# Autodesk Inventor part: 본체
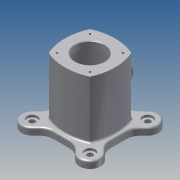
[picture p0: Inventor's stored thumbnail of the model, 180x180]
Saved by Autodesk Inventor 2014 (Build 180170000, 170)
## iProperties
Created: 2016-05
Part Number: 본체
Material: 알루미늄 6061
Document SubType Name: Modeling
Designer: 702
Density: 2.71 g/cm^3
Appearance: 알루미늄 - 평지
Mass: 1109.03 g
Surface Area: 865.354 cm^2
Volume: 409.236 cm^3
Author: 702
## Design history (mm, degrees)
sketch "스케치1"
  geometry: L1 (-49, -49)-(49, -49); L2 (49, -49)-(49, 49); L3 (49, 49)-(-49, 49); L4 (-49, 49)-(-49, -49); L5 (-49, -49)-(49, 49); L6 (49, -49)-(-49, 49); L7 (0, 0)-(-70, 0); L8 (0, 0)-(-49.497, 49.497); L9 (-36.77, 62.225)-(-23.544, 49); L10 (-62.225, 36.77)-(-49, 23.544); L11 (-49, 23.544)-(-49, 49); L12 (-49, 49)-(-23.544, 49); A1 r 70 centre (0, 0) between (-70, 0) and (-49.497, 49.497); A2 r 18 centre (-49.497, 49.497) between (-35.239, 60.483) and (-60.483, 35.239); A3 r 18 centre (-49.497, 49.497) between (-31.504, 49) and (-35.239, 60.483); A4 r 18 centre (-49.497, 49.497) between (-49, 31.504) and (-31.504, 49); A5 r 18 centre (-49.497, 49.497) between (-60.483, 35.239) and (-49, 31.504); 1 further point
  constraints: 24 end point, 18 point on circle, 6 tangent, 5 centre point, 4 midpoint, 4 point on line, 2 coincident, 2 collinear, 2 parallel, 2 perpendicular, 1 horizontal
  dimensions: "d0" = 98 distance of L2.end L3.end; "d1" = 98 distance of L1.end L2.end; "d2" = 140 diameter of A1; "d3" = 45 deg angle of L7 L8; "d4" = 36 diameter of A2; "d5" = 45 deg angle of L3 L9; "d6" = 45 deg angle of L10 L4
extrude "돌출1" new body sketch "스케치1" distance "d7" = 12; taper "d8" = 0 deg
extrude "돌출2" join sketch "스케치1" distance "d9" = 12; taper "d10" = 0 deg
hole "구멍1" diameter "d13" = 10; stored, may be unused: countersink angle "d17" = 90 deg, drill point angle "d19" = 118 deg; dims "d11" = 10, "d12" = 10, "d14" = 6, "d15" = 18, "d16" = 4, "d18" = 8
sketch "스케치3"
  geometry: L1 (-23.544, -49)-(-36.77, -62.225) reference; L2 (23.544, -49)-(-23.544, -49) reference; L3 (-40, 0)-(0, 0); L4 (0, 0)-(-28.284, 28.284); A1 r 40 centre (0, 0) between (-40, 0) and (-28.284, 28.284); 2 further points
  constraints: 4 end point, 2 coincident, 2 point on circle, 1 centre point, 1 parallel, 1 perpendicular
  dimensions: "d24" = 80 diameter of A1
hole "구멍2" sketch "스케치3" at (-28.284, 28.284) diameter "d25" = 3.242; stored, may be unused: countersink angle "d29" = 90 deg, drill point angle "d31" = 118 deg; dims "d26" = 7, "d27" = 4, "d28" = 2, "d30" = 10
sketch "스케치4"
  geometry: L1 (43, -43)-(-43, -43); L2 (-43, -43)-(-43, 43); L3 (-43, 43)-(43, 43); L4 (43, 43)-(43, -43); L5 (43, -43)-(-43, 43); L6 (-43, -43)-(43, 43); L7 (-35.355, -35.355)-(35.355, 35.355); L8 (-35.355, 35.355)-(35.355, -35.355); L9 (-23.544, -49)-(23.544, -49); L10 (-36.77, -62.225)-(-23.544, -49) reference; A1 r 85.579 centre (0, -42.579) between (35.355, 35.355) and (-35.355, 35.355); A2 r 85.579 centre (42.579, 0) between (-35.355, 35.355) and (-35.355, -35.355); A3 r 85.579 centre (-42.579, 0) between (35.355, -35.355) and (35.355, 35.355); A4 r 85.579 centre (0, 42.579) between (-35.355, -35.355) and (35.355, -35.355); 3 further points
  constraints: 18 end point, 8 point on circle, 6 midpoint, 4 centre point, 4 point on line, 4 tangent, 2 collinear, 2 parallel, 1 perpendicular
  dimensions: "d43" = 86 distance of L2.end L3.end; "d44" = 86 distance of L3.end L1.start; "d52" = 100 distance of L7.end L7.start; "d53" = 100 distance of L8.start L8.end
extrude "돌출3" join sketch "스케치4" distance "d54" = 98; taper "d55" = 0 deg
sketch "스케치5"
  geometry: L1 (-49, 0)-(-49, 12) reference; L2 (-49, 12)-(-43, 12) reference; L3 (-43, 110)-(43, 110) reference; L4 (43, 110)-(43, 12) reference; L5 (43, 12)-(49, 12) reference; L6 (49, 12)-(49, 0) reference; L7 (49, 0)-(-49, 0) reference; L8 (-49, 0)-(-49, 12) reference; L9 (-49, 12)-(-43, 12) reference; L10 (-43, 110)-(43, 110) reference; L11 (43, 110)-(43, 12) reference; L12 (43, 12)-(49, 12) reference; L13 (49, 12)-(49, 0) reference; L14 (49, 0)-(-49, 0) reference; L15 (25, 110)-(25, 98); L16 (25, 98)-(35, 98); L17 (35, 98)-(35, 12); L18 (35, 12)-(25, 12); L19 (25, 12)-(25, 0); L20 (0, 0)-(0, 110); L21 (-43, 12)-(-43, 110) reference; L22 (-43, 12)-(-43, 110) reference
  constraints: 12 end point, 3 parallel, 2 perpendicular, 2 point on line, 1 collinear, 1 midpoint
  dimensions: "d60" = 12 distance between parallel lines of L16 L3; "d61" = 12 distance of L18.end L19.end; "d62" = 86 distance of L16.end L17.end (derived); "d63" = 25 distance between parallel lines of L20 L15; "d64" = 35 distance between parallel lines of L20 L17; "d65" = 25 distance between parallel lines of L20 L19
revolve "회전1" sketch "스케치5" stored, may be unused: angle "d66" = 90 deg
sketch "스케치6" dims "d67" = 80
  geometry: L1 (-42.579, 0)-(0, 0); L2 (-35.355, 35.355)-(0, 0); C1 r 25 at (0, 0) reference; A1 r 85.579 centre (-42.579, 0) between (35.355, -35.355) and (35.355, 35.355) reference; 2 further points
  constraints: 4 end point, 1 coincident, 1 horizontal, 1 point on line, 3 other
hole "구멍3" sketch "스케치6" at (-28.284, 28.284) diameter "d68" = 3.242; stored, may be unused: countersink angle "d72" = 90 deg, drill point angle "d74" = 118 deg; dims "d69" = 7, "d70" = 4, "d71" = 2, "d73" = 10
sketch "스케치7"
  geometry: L1 (49, 12)-(49, 0) reference; L2 (49, 0)-(25, 0) reference; L3 (25, 0)-(25, 12) reference; L4 (25, 12)-(35, 12) reference; L5 (35, 12)-(35, 98) reference; L6 (35, 98)-(25, 98) reference; L7 (25, 98)-(25, 110) reference; L8 (25, 110)-(43, 110) reference; L9 (43, 110)-(43, 12) reference; L10 (43, 12)-(49, 12) reference; L11 (-49, 0)-(-49, 12) reference; L12 (-49, 12)-(-43, 12) reference; L13 (-43, 110)-(-25, 110) reference; L14 (-25, 110)-(-25, 98) reference; L15 (-25, 98)-(-35, 98) reference; L16 (-35, 98)-(-35, 12) reference; L17 (-35, 12)-(-25, 12) reference; L18 (-25, 12)-(-25, 0) reference; L19 (-25, 0)-(-49, 0) reference; L20 (35, 84.527)-(55, 81); L21 (55, 81)-(55, 61); L22 (55, 61)-(35, 61); L23 (-43, 12)-(-43, 110) reference; 1 further point
  constraints: 6 end point, 2 perpendicular, 2 point on line
  dimensions: "d79" = 49 distance between parallel lines of L8 L22; "d81" = 100 deg angle of L5 L20; "d82" = 55 distance from line of point (0, 0) L21; "d93" = 20 distance of L20.end L21.end
revolve "회전2" sketch "스케치7" stored, may be unused: angle "d83" = 90 deg
hole "구멍4" diameter "d86" = 25; stored, may be unused: countersink angle "d90" = 90 deg, drill point angle "d92" = 118 deg; dims "d84" = 10, "d85" = 10, "d87" = 7, "d88" = 30, "d89" = 8, "d91" = 50
fillet "모깎기1" dims "d94" = 25
fillet "모깎기2" dims "d95" = 3
fillet "모깎기3" dims "d96" = 3
fillet "모깎기4" dims "d97" = 3
fillet "모깎기5" dims "d98" = 3
chamfer "모따기1" distance "d99" = 1; stored, may be unused: second distance "d100" = 2, angle "d101" = 45 deg
node "작업 평면1"
sketch "스케치8"
  geometry: L1 (34.285, 110)-(-34.285, 110) reference; 2 further points
  constraints: 1 other
  dimensions: "d103" = 49 distance from line of point (-29, 61) L1; "d104" = 29 horizontal distance of point (0, 0) point (-29, 61)
feature "엠보싱1" sketch "스케치8" dims "d0" = 98, "d1" = 98, "d2" = 140, "d3" = 45 deg, "d4" = 36, "d5" = 45 deg, "d6" = 45 deg, "d105" = 0.5, "d106" = 0
fillet "모깎기6" dims "d107" = 3
node "솔리드1"
pattern_circular "원형 패턴1" dims angle "d22" = 360 deg
pattern_circular "원형 패턴2" dims angle "d33" = 360 deg
pattern_circular "원형 패턴3" dims angle "d76" = 360 deg
node "절단 모서리 투영1"
node "절단 모서리 투영2"
node "절단 모서리 투영3"
other parameters: "d102" = 59
